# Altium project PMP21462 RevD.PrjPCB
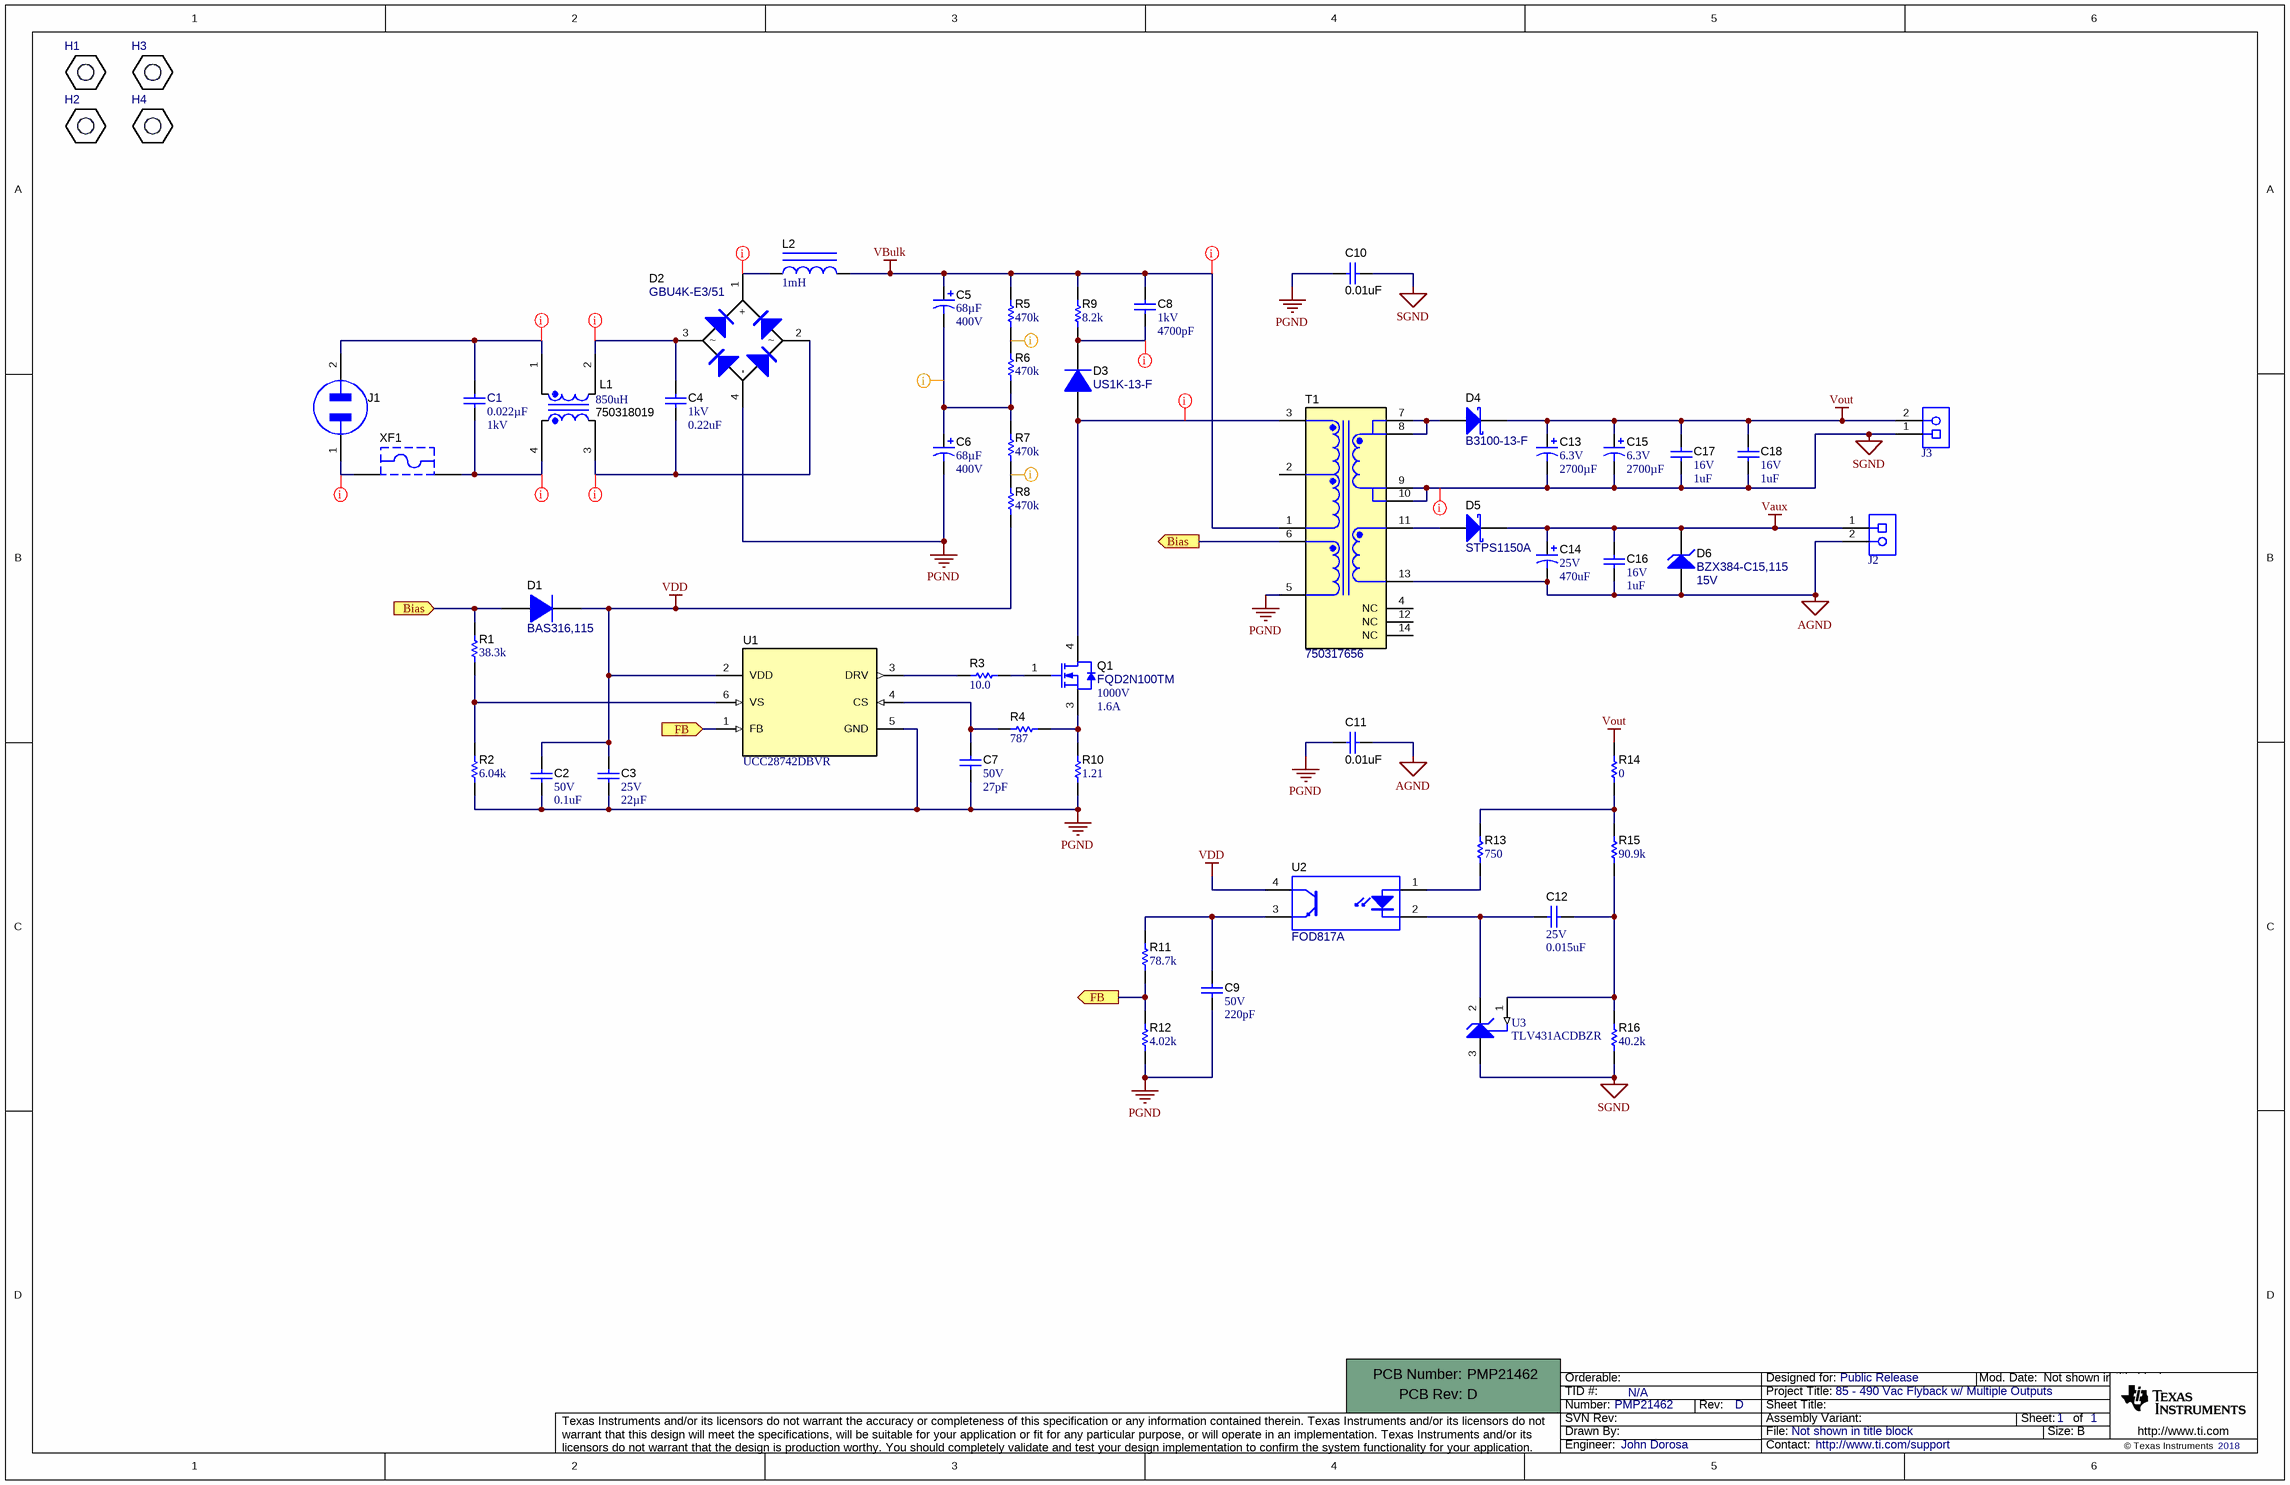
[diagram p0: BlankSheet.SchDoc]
TID: N/A; TechSupport: http://www.ti.com/support; SCH_Rev: D; PRJ_Title: 85 - 490 Vac Flyback w/ Multiple Outputs; PRJ_Number: PMP21462; PRJ_Engineer: John Dorosa; PRJ_Customer: Public Release; PCB_Rev: D; PCB_Layout: John Dorosa; CopyrightYear: 2018
1 sheet, 56 parts. Net scope: flat (ports and power ports of the same name join across sheets).
Board file: PCB.PcbDoc

## Sheet BlankSheet.SchDoc
size 431 x 279 mm; Date: Not shown in title block; ApprovedBy: Not shown in title block; CheckedBy: Not shown in title block; Author: Not shown in title block; CompanyName: Not shown in title block; Engineer: Not shown in title block; Organization: Not shown in title block; Address1: Not shown in title block; Address2: Not shown in title block; Address3: Not shown in title block; Address4: Not shown in title block; DocumentNumber: 1; Revision: Use project parameter SCH_Rev; SheetNumber: 1; SheetTotal: 1; PageSetup: Record=PageOptions¦CenterHorizontal=True¦CenterVertical=True¦PrintScale=1.00¦XCorrection=1.00¦YCorrection=1.00¦PrintKind=0¦BorderSize=5000000¦LeftOffset=0¦BottomOffset=0¦Orientation=2¦PaperLength=1000¦PaperWidth=1000¦Scale=100¦PaperSource=15¦PrintQuality=600¦MediaType=1¦DitherType=10¦PaperKind=Letter¦PrintScaleMode=1

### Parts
!PCB1  Printed Circuit Board  (value not drawn)  (mechanical)
C1  value 0.022µF  VoltageRating: 1kV  [FP-B32642B0223J_RADIAL-MFG]  (hidden comment: B32642B0223J)
C2  VDC_V: 50V  ValueDisplayed: 0.1uF  [0402]  (hidden comment: GCM155R71H104KE02D)
C3  VDC_V: 25V  ValueDisplayed: 22µF  [1210_280]  (hidden comment: C1210C226K3RAC7800)
C4  VDC_V: 1kV  ValueDisplayed: 0.22uF  [B32653_2650x2050x1100]  (hidden comment: B32653A224J189)
C5  ValueDisplayed: 68µF  VDC_V: 400V  [BXW_1450x3000_HU]  (hidden comment: 400BXW68MEFR14.5X30)
C6  ValueDisplayed: 68µF  VDC_V: 400V  [BXW_1450x3000_HU]  (hidden comment: 400BXW68MEFR14.5X30)
C7  VDC_V: 50V  ValueDisplayed: 27pF  [0402]  (hidden comment: GRM1555C1H270JA01D)
C8  VDC_V: 1kV  ValueDisplayed: 4700pF  [1210]  (hidden comment: VJ1210Y472KXGAT5Z)
C9  VDC_V: 50V  ValueDisplayed: 220pF  [0603]  (hidden comment: GRM188R71H221KA01D)
C10  ValueDisplayed: 0.01uF  [B32652A_500x1050x1800]  (hidden comment: B32652A0103K)
C11  ValueDisplayed: 0.01uF  [B32652A_500x1050x1800]  (hidden comment: B32652A0103K)
C12  VDC_V: 25V  ValueDisplayed: 0.015uF  [0603]  (hidden comment: GRM188R71E153KA01D)
C13  VDC_V: 6.3V  ValueDisplayed: 2700µF  [ZLJ_1000X2000]  (hidden comment: 6.3ZLJ2700M10X20)
C14  VDC_V: 25V  ValueDisplayed: 470uF  [ZLJ_1000x1250]  (hidden comment: 25ZLJ470M10X12.5)
C15  VDC_V: 6.3V  ValueDisplayed: 2700µF  [ZLJ_1000X2000]  (hidden comment: 6.3ZLJ2700M10X20)
C16  VDC_V: 16V  ValueDisplayed: 1uF  [0805_HV]  (hidden comment: B37941K9105K62)
C17  VDC_V: 16V  ValueDisplayed: 1uF  [0805_HV]  (hidden comment: B37941K9105K62)
C18  VDC_V: 16V  ValueDisplayed: 1uF  [0805_HV]  (hidden comment: B37941K9105K62)
D1  BAS316,115  [SOD-323]
D2  GBU4K-E3/51  [GBU]
D3  US1K-13-F  [SMA]
D4  B3100-13-F  [SMC]
D5  STPS1150A  [SMA]
D6  BZX384-C15,115  value 15V  [SOD-323]
H1  4826  [KEYSTONE_4826]  (value not drawn)
H2  4826  [KEYSTONE_4826]  (value not drawn)
H3  4826  [KEYSTONE_4826]  (value not drawn)
H4  4826  [KEYSTONE_4826]  (value not drawn)
J1  770W-X2/10  [CONN_AC_770W-SERIES]  (value not drawn)
J2  ED120/2DS  [On-Shore_ED120_2DS]  (value not drawn)
J3  ED120/2DS  [On-Shore_ED120_2DS]  (value not drawn)
L1  750318019  value 850uH  [Wurth_750318019]
L2  ValueDisplayed: 1mH  [WE-TI_8095]  (hidden comment: 768772102)
Q1  FQD2N100TM  value 1000V  IdsMax_A: 1.6A  [DPAK]
R1  ValueDisplayed: 38.3k  [0603]  (hidden comment: CRCW060338K3FKEA)
R2  ValueDisplayed: 6.04k  [0603]  (hidden comment: CRCW06036K04FKEA)
R3  ValueDisplayed: 10.0  [0603]  (hidden comment: CRCW060310R0FKEA)
R4  ValueDisplayed: 787  [0603]  (hidden comment: CRCW0603787RFKEA)
R5  ValueDisplayed: 470k  [0805_HV]  (hidden comment: CRCW0805470KJNEA)
R6  ValueDisplayed: 470k  [0805_HV]  (hidden comment: CRCW0805470KJNEA)
R7  ValueDisplayed: 470k  [0805_HV]  (hidden comment: CRCW0805470KJNEA)
R8  ValueDisplayed: 470k  [0805_HV]  (hidden comment: CRCW0805470KJNEA)
R9  ValueDisplayed: 8.2k  [2512]  (hidden comment: CRCW25128K20JNEG)
R10  ValueDisplayed: 1.21  [0805_HV]  (hidden comment: RC0805FR-071R21L)
R11  ValueDisplayed: 78.7k  [0603]  (hidden comment: CRCW060378K7FKEA)
R12  ValueDisplayed: 4.02k  [0603]  (hidden comment: CRCW06034K02FKEA)
R13  ValueDisplayed: 750  [0603]  (hidden comment: CRCW0603750RFKEA)
R14  ValueDisplayed: 0  [0603]  (hidden comment: CRCW06030000Z0EA)
R15  ValueDisplayed: 90.9k  [0603]  (hidden comment: CRCW060390K9FKEA)
R16  ValueDisplayed: 40.2k  [0603]  (hidden comment: CRCW060340K2FKEA)
T1  750317656  [Wurth_EE20-10-6_5643]
U1  UCC28742DBVR  [DBV0006A_N]
U2  FOD817A  [DIP-4]
U3  TLV431ACDBZR  [DBZ0003A_N]
XF1  56000001009  [FuseHolder_560000010]  (value not drawn)

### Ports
Bias (in), Bias (out), FB (in), FB (out)

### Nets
AGND: C11.1 C14.2(-) C16.2 D6.2(A) J2.2 T1.13
PGND: C2.2 C3.2 C6.2(-) C7.2 C9.2 C10.2 C11.2 D2.4(-) R2.1 R10.1 R12.1 T1.5 U1.5(GND)
SGND: C10.1 C13.2(-) C15.2(-) C17.2 C18.2 J3.1 R16.1 T1.9 T1.10 U3.3(ANODE)
Vaux: C14.1(+) C16.1 D5.1(K) D6.1(K) J2.1
VBulk: C5.1(+) C8.1 L2.2 R5.2 R9.2 T1.1
VDD: C2.1 C3.1 D1.1(K) R8.1 U1.2(VDD) U2.4(C)
Vout: C13.1(+) C15.1(+) C17.1 C18.1 D4.1(K) J3.2 R14.2
Bias: D1.2(A) R1.2 T1.6 ; port Bias
FB: R11.1 R12.2 U1.1(FB) ; port FB
NetC1_1: C1.1 L1.4 XF1.1
NetC1_2: C1.2 J1.2(Hot) L1.1
NetC4_1: C4.1 D2.3 L1.2
NetC4_2: C4.2 D2.2 L1.3
NetC5_2: C5.2(-) C6.1(+) R6.1 R7.2
NetC7_1: C7.1 R4.1 U1.4(CS)
NetC8_2: C8.2 D3.1(K) R9.1
NetC9_1: C9.1 R11.2 U2.3(E)
NetC12_1: C12.1 R15.1 R16.2 U3.1(REF)
NetC12_2: C12.2 U2.2(K) U3.2(CATHODE)
NetD2_1: D2.1(+) L2.1
NetD3_2: D3.2(A) Q1.4(D) T1.3
NetD4_2: D4.2(A) T1.7 T1.8
NetD5_2: D5.2(A) T1.11
NetJ1_1: J1.1(Neutral) XF1.2
NetQ1_1: Q1.1(G) R3.2
NetQ1_3: Q1.3(S) R4.2 R10.2
NetR1_1: R1.1 R2.2 U1.6(VS)
NetR3_1: R3.1 U1.3(DRV)
NetR5_1: R5.1 R6.2
NetR7_1: R7.1 R8.2
NetR13_1: R13.1 U2.1(A)
NetR13_2: R13.2 R14.1 R15.2

Not connected (* = marked no-connect by the designer): T1 2 4(NC) 12(NC) 14(NC)

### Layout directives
mark named HV: NetC1_1, NetC1_2, NetC4_1, NetC4_2, NetC8_2, NetD2_1, NetD3_2, NetJ1_1, SGND, VBulk
mark named MV: NetC5_2, NetR5_1, NetR7_1

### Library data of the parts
!PCB1 = CMP-0003618-2: Manufacturer: Any; PartNumber: PMP21462
C1 = CMP-0086383-2: 0.022µF Film Capacitor 600V 1000V (1kV) Polypropylene (PP), Metallized Radial; Manufacturer: TDK; AEC Qualified: Yes; TaMin_C: -55°C; TaMax_C: 110°C; VAC: 500V; Cap_F: 22nF; Symbol Name: SYM-B32642B0223J; AEC Grade: Grade 2; Tolerance_%: 5%; SizeZ_mm: 11mm
C2 = CMP-0006356-2: CAP, CERM, 0.1 uF, 50 V, +/- 10%, X7R, AEC-Q200 Grade 1, 0402; Manufacturer: MuRata; TaMin_C: -55°C; Polarized: N; SizeAreaWB_mm2: 3; Value1: Unknown; U/M: EA; Value: 0.1uF; TaMax_C: 125°C; SizeZ_mm: 0.6; SizeX_mm: 1; SizeY_mm: 0.5; AEC Qualified: Y; Cap_F: 100nF; AEC Category: Q200
C3 = CMP-0082266-1: CAP, CERM, 22 µF, 25 V,+/- 10%, X7R, 1210; Manufacturer: Kemet; TaMin_C: -55°C; ESR_ohm: 1m; Polarized: N; Green_Lifecycle: Active; SizeAreaWB_mm2: 14.7; Green_REACh: Incomplete; Value1: 0.001 ohm; U/M: EA; Value: 22uF; TaMax_C: 125°C; SizeZ_mm: 2.8; SizeX_mm: 3.2; SizeY_mm: 2.5; Cap_Case: 1210; SizeArea_mm2: 8; AEC Category: Q200
C4 = CMP-0012347-3: CAP, Film, 0.22 uF, 1000 V, +/- 5%, TH; Manufacturer: TDK; TaMin_C: -55°C; Polarized: N; SizeAreaWB_mm2: 641.25; Value1: Unknown; Value: 0.22uF; TaMax_C: 110°C; SizeZ_mm: 11; SizeX_mm: 26.5; SizeY_mm: 20.5; Cap_Case: 26.5x20.5x11mm; Value2: 1000V; SizeArea_mm2: 543.25; Cap_F: 220nF; AEC Category: Q200
C5 C6 = CMP-0750100-2: CAP, AL, 68 µF, 400 V, +/- 20%, TH; Manufacturer: Rubycon; SizeX_mm: 14.5; Cap_Case: 14.5x30mm; SizeZ_mm: 32; CompType: Capacitor; SizeAreaWB_mm2: 272.25; AEC Qualified: N; TaMin_C: -40°C; Polarized: Y; AEC Category: Q200; Value: 68uF; TaMax_C: 105°C; SizeArea_mm2: 210.25; U/M: EA
C7 = CMP-0006443-2: CAP, CERM, 27 pF, 50 V, +/- 5%, C0G/NP0, 0402; Manufacturer: MuRata; TaMin_C: -55°C; Polarized: N; SizeAreaWB_mm2: 3; Value1: Unknown; U/M: EA; Value: 27pF; TaMax_C: 125°C; SizeZ_mm: 0.6; SizeX_mm: 1; SizeY_mm: 0.5; AEC Category: Q200
C8 = CMP-0009286-2: CAP, CERM, 4700 pF, 1000 V, +/- 10%, X7R, 1210; Manufacturer: Vishay-Vitramon; TaMin_C: -55°C; Polarized: N; SizeAreaWB_mm2: 14.7; Value1: Unknown; U/M: EA; Value: 4700pF; TaMax_C: 125°C; SizeZ_mm: 1.35; SizeX_mm: 3.2; SizeY_mm: 2.5; Value2: 1000V; SizeArea_mm2: 8; Cap_F: 4.7nF; AEC Category: Q200
C9 = CMP-0007442-5: CAP, CERM, 220 pF, 50 V, +/- 10%, X7R, 0603; Manufacturer: MuRata; TaMin_C: -55°C; Polarized: N; SizeAreaWB_mm2: 4.68; Value1: Unknown; U/M: EA; Value: 220pF; TaMax_C: 125°C; SizeZ_mm: 1; SizeX_mm: 1.6; SizeY_mm: 0.8; SizeArea_mm2: 1.28; AEC Category: Q200
C10 C11 = CMP-0012344-3: CAP, Film, 0.01 uF, 1000 V, +/- 10%, TH; Manufacturer: TDK; TaMin_C: -55°C; Polarized: N; SizeAreaWB_mm2: 140; Value1: Unknown; Value: 0.01uF; TaMax_C: 110°C; SizeZ_mm: 10.5; SizeX_mm: 18; SizeY_mm: 5; Cap_Case: 5x10.5x18; Value2: 1000V; SizeArea_mm2: 90; CompType: Capacitor; Cap_F: 10nF; VDC_V: 1kV; AEC Category: Q200
C12 = CMP-0007410-5: CAP, CERM, 0.015 uF, 25 V, +/- 10%, X7R, 0603; Manufacturer: MuRata; TaMin_C: -55°C; Polarized: N; SizeAreaWB_mm2: 4.68; Value1: Unknown; U/M: EA; TaMax_C: 125°C; SizeZ_mm: 1; SizeX_mm: 1.6; SizeY_mm: 0.8; SizeArea_mm2: 1.28; Cap_F: 15nF; AEC Category: Q200
C13 C15 = CMP-0084270-1: CAP, AL, 2700 µF, 6.3 V, +/- 20%, TH; Manufacturer: Rubycon; SizeY_mm: 10; Value: 2700uF; SizeZ_mm: 22; U/M: EA; AEC Category: Q200; SizeAreaWB_mm2: 144; TaMax_C: 105°C; TaMin_C: -40°C; Cap_F: 2.7mF; AEC Qualified: N; SizeArea_mm2: 100; Polarized: Y; Cap_Case: 10x20mm; CompType: Capacitor
C14 = CMP-0010295-1: CAP, AL, 470 uF, 25 V, +/- 20%, 0.053 ohm, TH; Manufacturer: Rubycon; TaMin_C: -40°C; ESR_ohm: 0.053; Polarized: Y; SizeAreaWB_mm2: 144; U/M: EA; Value: 470uF; TaMax_C: 105°C; SizeZ_mm: 14; SizeX_mm: 10; SizeArea_mm2: 100; CompType: Capacitor; AEC Qualified: N; Cap_F: 470µF; IRMS_A: 1.7A; AEC Category: Q200
C16-C18 = CMP-0007697-2: CAP, CERM, 1 uF, 16 V, +/- 10%, X7R, 0805; Manufacturer: TDK; TaMin_C: -55°C; Polarized: N; SizeAreaWB_mm2: 6.75; Value1: Unknown; U/M: EA; Value: 1uF; TaMax_C: 125°C; SizeZ_mm: 1.45; SizeX_mm: 2; SizeY_mm: 1.25; Cap_Case: 0805; SizeArea_mm2: 2.5; Cap_F: 1µF; AEC Category: Q200
D1 = CMP-0029006-1: Diode, Ultrafast, 100 V, 0.25 A, SOD-323; Manufacturer: Nexperia; Io_A: 250mA; Green_Lifecycle: Not Set; SizeAreaWB_mm2: 8.695; Vr_V: 100V; Green_REACh: Incomplete; Value1: 0.25A; TJmax_C: 150°C; U/M: EA; Value: 100V; SizeZ_mm: 1; SizeX_mm: 2.7; SizeY_mm: 1.35; Vf_V: 1.4V; SizeArea_mm2: 3.645; AEC Category: Q101
D2 = CMP-0029237-3: Diode, Switching-Bridge, 800 V, 3 A, TH; Manufacturer: Vishay-Semiconductor; Value1: 3A; SizeZ_mm: 21.55; Green_Lifecycle: Not Set; Value: 800V; TJmax_C: 150°C; SizeY_mm: 3.43; Green_REACh: Incomplete; SizeArea_mm2: 75.6315; AEC Category: Q101; Vf_V: 1V; RJC_CperW: 4.2; SizeX_mm: 22.05; SizeAreaWB_mm2: 130.5915
D3 = CMP-0076980-1: Diode, Fast Rectifier, 800 V, 1 A, SMA; Manufacturer: Diodes Inc.; SizeAreaWB_mm2: 37.3428; Vr_V: 800V; SizeArea_mm2: 16.3228; TJmax_C: 150°C; AEC Category: Q101; Value: 800V; SizeZ_mm: 2.87; Green_REACh: Incomplete; Io_A: 1A; Vf_V: 1.7V; SizeY_mm: 2.92; Green_Lifecycle: Not Set; U/M: EA; SizeX_mm: 5.59
D4 = CMP-0028411-1: Diode, Schottky, 100 V, 3 A, SMC; Manufacturer: Diodes Inc.; Io_A: 3A; Green_Lifecycle: Active; SizeAreaWB_mm2: 83.2686; Vr_V: 100V; Green_REACh: Passed; TJmax_C: 125°C; U/M: EA; Value: 100V; SizeZ_mm: 2.6; SizeX_mm: 8.13; SizeY_mm: 6.22; Vf_V: 790mV; Value2: 0.79V; SizeArea_mm2: 50.5686; AEC Category: Q101; RJC_CperW: 10
D5 = CMP-0028752-1: Diode, Schottky, 150 V, 1 A, SMA; Manufacturer: STMicroelectronics; Io_A: 1A; Green_Lifecycle: Not Set; SizeAreaWB_mm2: 37.3428; Vr_V: 150V; Green_REACh: Incomplete; TJmax_C: 175°C; U/M: EA; Value: 150V; SizeZ_mm: 2.87; SizeX_mm: 5.59; SizeY_mm: 2.92; Vf_V: 780mV; Value2: 0.78V; SizeArea_mm2: 16.3228; AEC Qualified: N; AEC Category: Q101; RJC_CperW: 30
D6 = CMP-0005844-2: Diode, Zener, 15 V, 300 mW, SOD-323; Manufacturer: NXP Semiconductor; Power_W: 300mW; SizeAreaWB_mm2: 8.695; Value1: 0.3W; RJA_CperW: 415; U/M: EA; SizeZ_mm: 1; SizeX_mm: 2.7; SizeY_mm: 1.35; SizeArea_mm2: 3.645; AEC Category: Q101
H1-H4 = CMP-0003686-1: Manufacturer: Keystone; CompType: Standoff
J1 = CMP-0074930-1: AC Receptacle, 2.5A, R/A, TH; Manufacturer: Qualtek Electronics Corporation; CNHeader: False; Green_Lifecycle: Not Set; Green_REACh: Incomplete
J2 J3 = CMP-0074910-1: Terminal Block, 5.08 mm, 2x1, Brass, TH; Manufacturer: On-Shore Technology; Cert_VDE: Y; CNHeader: False; Current_A: 15A; Green_Lifecycle: Not Set; Shrouded: N; Gender: Female; Green_REACh: Incomplete; Voltage_V: 300V; Row_Count: 1; Pitch_mm: 5.08; CT: True
L1 = CMP-0086067-1: Coupled inductor, 850 µH, 0.0154 ohm, TH; Manufacturer: Wurth Elektronik; Ind_H: 850µH; AEC Category: Q200; DCR_ohm: 0.0154; SizeZ_mm: 21.85; SizeY_mm: 14.5; SizeArea_mm2: 268.25; AEC Qualified: N; SizeAreaWB_mm2: 338.25; SizeX_mm: 18.5
L2 = CMP-0064846-1: Inductor, Shielded Drum Core, Metal Composite, 1 mH, 0.5 A, 1.7 ohm, TH; Manufacturer: Wurth Elektronik; Isat: 0.55A @ 10% inductance drop; Irms: 0.5A @ 40C rise; Green_Lifecycle: Active; SizeAreaWB_mm2: 96.04; DCR_ohm: 1.7; Green_REACh: Passed; Value1: 1.7 ohm; Value: 1mH; Imax_A: 500mA; SizeZ_mm: 10; SizeX_mm: 7.8; Value2: 0.5A; SizeArea_mm2: 60.84; AEC Category: Q200
Q1 = CMP-0001290-1: MOSFET, N-CH, 1000 V, 1.6 A, DPAK; Alternate Manufacturer: None; Manufacturer: Fairchild Semiconductor; SizeZ_mm: 2.29; ChType: N; Value2: 12 nC; VdsMax_V: 1kV; SizeX_mm: 9.91; SizeY_mm: 6.54; Vgs_V: 30V; SizeArea_mm2: 64.8114; AEC Category: Q101; SizeAreaWB_mm2: 101.7114; U/M: EA; QgTyp_nC: 12
R1 = CMP-0022364-4: RES, 38.3 k, 1%, 0.1 W, AEC-Q200 Grade 0, 0603; Manufacturer: Vishay-Dale; Power_W: 100mW; TempCo: 100 ppm/C; Value_Code: 38k3; Value: 38.3k; EIA_Code: E96; SizeX_mm: 1.6; SizeY_mm: 0.8; SizeZ_mm: 1; Value2: 0.1W; SizeArea_mm2: 1.28; AEC Qualified: Y; VDC_V: 75V; AEC Category: Q200; AEC Grade: 0
R2 = CMP-0022558-4: RES, 6.04 k, 1%, 0.1 W, AEC-Q200 Grade 0, 0603; Manufacturer: Vishay-Dale; Power_W: 100mW; TempCo: 100 ppm/C; Value_Code: 6k04; Value: 6.04k; EIA_Code: E96; SizeX_mm: 1.6; SizeY_mm: 0.8; SizeZ_mm: 1; Value2: 0.1W; SizeArea_mm2: 1.28; AEC Qualified: Y; VDC_V: 75V; AEC Category: Q200; AEC Grade: 0
R3 = CMP-0022003-4: RES, 10.0, 1%, 0.1 W, AEC-Q200 Grade 0, 0603; Manufacturer: Vishay-Dale; Power_W: 100mW; TempCo: 100 ppm/C; Value_Code: 10R0; Value: 10.0; EIA_Code: E96; Res_ohm: 10; SizeX_mm: 1.6; SizeY_mm: 0.8; SizeZ_mm: 1; Value2: 0.1W; SizeArea_mm2: 1.28; AEC Qualified: Y; VDC_V: 75V; AEC Category: Q200; AEC Grade: 0
R4 = CMP-0022596-5: RES, 787, 1%, 0.1 W, AEC-Q200 Grade 0, 0603; Manufacturer: Vishay-Dale; Power_W: 100mW; TempCo: 100 ppm/C; Value_Code: 787R; Value: 787; EIA_Code: E96; SizeX_mm: 1.6; SizeY_mm: 0.8; SizeZ_mm: 1; Value2: 0.1W; SizeArea_mm2: 1.28; AEC Qualified: Y; VDC_V: 75V; AEC Category: Q200; AEC Grade: 0
R5-R8 = CMP-0020554-3: RES, 470 k, 5%, 0.125 W, AEC-Q200 Grade 0, 0805; Manufacturer: Vishay-Dale; Power_W: 125mW; TempCo: 200 ppm/C; Value: 470k; EIA_Code: E24; SizeX_mm: 2; SizeY_mm: 1.25; SizeZ_mm: 1.45; Value2: 0.125W; SizeArea_mm2: 2.5; AEC Qualified: Y; VDC_V: 150V; AEC Category: Q200; AEC Grade: 0
R9 = CMP-0016010-3: RES, 8.2 k, 5%, 1 W, AEC-Q200 Grade 0, 2512; Manufacturer: Vishay-Dale; Power_W: 1W; TempCo: 200 ppm/C; Value_Code: 8k20; Value: 8.2k; EIA_Code: E24; SizeX_mm: 6.3; SizeY_mm: 3.2; SizeZ_mm: 0.71; SizeArea_mm2: 20.16; AEC Qualified: Y; VDC_V: 500V; AEC Grade: 0; AEC Category: Q200
R10 = CMP-0021872-2: RES, 1.21, 1%, 0.125 W, 0805; Manufacturer: Yageo America; Power_W: 125mW; TempCo: 200 ppm/C; Value_Code: 1R21; U/M: EA; Value: 1.21; EIA_Code: E96; SizeX_mm: 2; SizeY_mm: 1.25; SizeZ_mm: 1.45; Value2: 0.125W; SizeArea_mm2: 2.5; VDC_V: 150V; AEC Category: Q200
R11 = CMP-0022597-4: RES, 78.7 k, 1%, 0.1 W, AEC-Q200 Grade 0, 0603; Manufacturer: Vishay-Dale; Power_W: 100mW; TempCo: 100 ppm/C; Value_Code: 78k7; Value: 78.7k; EIA_Code: E96; SizeX_mm: 1.6; SizeY_mm: 0.8; SizeZ_mm: 1; Value2: 0.1W; SizeArea_mm2: 1.28; AEC Qualified: Y; VDC_V: 75V; AEC Category: Q200; AEC Grade: 0
R12 = CMP-0022449-4: RES, 4.02 k, 1%, 0.1 W, AEC-Q200 Grade 0, 0603; Manufacturer: Vishay-Dale; Power_W: 100mW; TempCo: 100 ppm/C; Value_Code: 4k02; Value: 4.02k; EIA_Code: E96; SizeX_mm: 1.6; SizeY_mm: 0.8; SizeZ_mm: 1; Value2: 0.1W; SizeArea_mm2: 1.28; AEC Qualified: Y; VDC_V: 75V; AEC Category: Q200; AEC Grade: 0
R13 = CMP-0022588-5: RES, 750, 1%, 0.1 W, AEC-Q200 Grade 0, 0603; Manufacturer: Vishay-Dale; Power_W: 100mW; TempCo: 100 ppm/C; Value_Code: 750R; Value: 750; EIA_Code: E96; SizeX_mm: 1.6; SizeY_mm: 0.8; SizeZ_mm: 1; Value2: 0.1W; SizeArea_mm2: 1.28; AEC Qualified: Y; VDC_V: 75V; AEC Category: Q200; AEC Grade: 0
R14 = CMP-0025697-4: RES, 0, 5%, 0.1 W, AEC-Q200 Grade 0, 0603; Manufacturer: Vishay-Dale; Power_W: 100mW; TempCo: 200 ppm/C; Value_Code: 0000; Value: 0; EIA_Code: E24; SizeX_mm: 1.6; SizeY_mm: 0.8; SizeZ_mm: 1; Value2: 0.1W; SizeArea_mm2: 1.28; AEC Qualified: Y; VDC_V: 75V; AEC Category: Q200
R15 = CMP-0022651-4: RES, 90.9 k, 1%, 0.1 W, AEC-Q200 Grade 0, 0603; Manufacturer: Vishay-Dale; Power_W: 100mW; TempCo: 100 ppm/C; Value_Code: 90k9; Value: 90.9k; EIA_Code: E96; SizeY_mm: 0.8; SizeZ_mm: 1; Value2: 0.1W; SizeArea_mm2: 1.28; SizeX_mm: 1.6; AEC Qualified: Y; VDC_V: 75V; AEC Category: Q200; AEC Grade: 0
R16 = CMP-0022410-4: RES, 40.2 k, 1%, 0.1 W, AEC-Q200 Grade 0, 0603; Manufacturer: Vishay-Dale; Power_W: 100mW; TempCo: 100 ppm/C; Value_Code: 40k2; Value: 40.2k; EIA_Code: E96; SizeX_mm: 1.6; SizeY_mm: 0.8; SizeZ_mm: 1; Value2: 0.1W; SizeArea_mm2: 1.28; AEC Qualified: Y; VDC_V: 75V; AEC Category: Q200; AEC Grade: 0
T1 = CMP-0081896-1: Transformer, 2900 uH, TH; Manufacturer: Wurth Elektronik; Rsec2_ohm: 0.266; SizeAreaWB_mm2: 653.4; DCR_ohm: 2.2; Lp: 2900; SizeZ_mm: 16; SizeX_mm: 25; SizeY_mm: 22.2; Ns1toNp: 0.0348; SizeArea_mm2: 555; Ind_H: 2.9mH; AEC Qualified: N; Rsec1_ohm: 0.017; AEC Category: Q200
U1 = CMP-0078369-1: High-Efficiency Low-Cost Flyback Controller with Secondary-Side Regulation, DBV0006A (SOT-23-6); Manufacturer: Texas Instruments; SizeZ_mm: 1.45; SizeX_mm: 2.8; SizeY_mm: 2.9; AEC Category: Q200; AEC Qualified: N; SizeArea_mm2: 8.12; CompType: IC; SizeAreaWB_mm2: 14.82
U2 = CMP-0006173-1: Optocoupler, 5 kV, 80-160% CTR, TH; Manufacturer: Fairchild Semiconductor; CTR (Max): 160%; SizeAreaWB_mm2: 71.064; CTR (Min): 80%; SizeZ_mm: 5; SizeX_mm: 8.8; SizeY_mm: 4.58; SizeArea_mm2: 40.304; Voltage_Isolation_Vrms: 5kV
U3 = CMP-0033048-1: Low Voltage Adjustable Precision Shunt Regulator, 39 ppm / degC, 15 mA, 0 to 70 degC, 3-pin SOT-23 (DBZ), Green (RoHS & no Sb/Br); Manufacturer: Texas Instruments; Min Iz for Regulation(uA): 80; Rating: Catalog; VO Adj(Max)(V): 6; Iout/Iz(Max)(mA): 15; VO Adj(Min)(V): 1.24; Temp Coeff(Typ)(ppm/ degree C): 39; Temp Coeff(Max)(ppm/ degree C): 129; SubFamily: Shunt Voltage Reference
XF1 = CMP-0003627-1: Fuse Holder, TR5, TH; Manufacturer: Littelfuse

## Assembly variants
001: not fitted H1 H2 H3 H4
